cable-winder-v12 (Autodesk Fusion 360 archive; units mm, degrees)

design "Cable Winder"
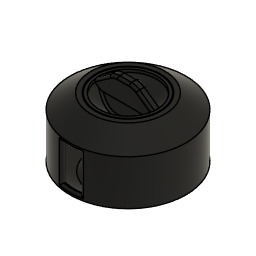
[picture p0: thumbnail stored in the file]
part number: Small Smooth
parameter "radius" = 25
parameter "height" = 32
parameter "gap" = 0.35
sketch "Skizze" plane through (0, 0, 0) normal (0, 1, 0) x axis (1, 0, 0)
  line L1 (25, 0) -> (0, 0)
  line L2 (25, -9.6981) -> (25, 0)
  line L3 (16, -16) -> (25, -9.6981)
  line L4 (14, -16) -> (16, -16)
  line L5 (23, -8.657) -> (23, 0)
  line L6 (14, -14.9589) -> (23, -8.657)
  line L7 (14, -14.9589) -> (14, -16)
  line L8 (12.45, -16) -> (13.65, -16)
  line L9 (13.65, -14.7767) -> (13.65, -16)
  line L10 (15.6652, -13.3656) -> (13.65, -14.7767)
  line L11 (8, -7.9984) -> (15.6652, -13.3656)
  line L12 (8, 0) -> (8, -7.9984)
  line L13 (12.45, -14.7767) -> (12.45, -16)
  line L14 (5.626, -9.9984) -> (12.45, -14.7767)
  line L15 (0, -9.9984) -> (5.626, -9.9984)
  line L16 (12.45, -14.7767) -> (13.65, -14.7767)
  line L17 (0, 0) -> (0, -9.9984)
  line L18 (0, -16) -> (0, -9.9984)
  line L19 (12.45, -16) -> (0, -16)
  line L20 (0, -7.9984) -> (8, -7.9984)
  line L21 (15.3795, -13.1656) -> (15.3795, -13.5656)
  line L22 (0, 0) -> (0, 9.9984)
  line L23 (0, 7.9984) -> (8, 7.9984)
  line L24 (8, 0) -> (8, 7.9984)
  line L25 (8, 7.9984) -> (15.6652, 13.3656)
  line L26 (12.45, 16) -> (13.65, 16)
  line L27 (0, 16) -> (0, 9.9984)
  line L28 (12.45, 16) -> (0, 16)
  line L29 (13.65, 14.7767) -> (13.65, 16)
  line L30 (15.6652, 13.3656) -> (13.65, 14.7767)
  line L31 (14, 14.9589) -> (14, 16)
  line L32 (14, 16) -> (16, 16)
  line L33 (16, 16) -> (25, 9.6981)
  line L34 (14, 14.9589) -> (23, 8.657)
  line L35 (23, 8.657) -> (23, 0)
  line L36 (25, 9.6981) -> (25, 0)
  line L37 (-2, -9.9984) -> (2, -9.9984)
  line L38 (4.4501, -21.6016) -> (12.45, -16)
  line L39 (0, -21.6016) -> (4.4501, -21.6016)
  line L40 (12.45, 14.7767) -> (12.45, 16)
  line L41 (5.626, 9.9984) -> (12.45, 14.7767)
  line L42 (0, 9.9984) -> (5.626, 9.9984)
  line L43 (-4.4501, -21.6016) -> (-12.45, -16)
  line L44 (0, -21.6016) -> (-4.4501, -21.6016)
  line L45 (-5.626, -9.9984) -> (-12.45, -14.7767)
  line L46 (-12.45, -14.7767) -> (-12.45, -16)
  line L47 (0, -9.9984) -> (-5.626, -9.9984)
  line L48 (0, 9.9984) -> (-5.626, 9.9984)
  line L49 (-5.626, 9.9984) -> (-12.45, 14.7767)
  line L50 (-12.45, 14.7767) -> (-12.45, 16)
  line L51 (-12.45, 16) -> (0, 16)
  line L52 (4, -8) -> (-4, -8)
  line L53 (4, 8) -> (4, -8)
  line L54 (-4, 8) -> (4, 8)
  line L55 (-4, -8) -> (-4, 8)
  line L56 (4, 8) -> (-4, -8)
  line L57 (-4, 8) -> (4, -8)
  point P1 (0, 0)
  point P2 (0, 0)
  point P6 (23, 0)
  point P14 (8, 0)
  point P19 (0, 0)
  point P21 (0, -7.9984)
  point P22 (15.3795, -13.5656)
  point P23 (15.3795, -13.1656)
  point P26 (0, 0)
  point P30 (0, 0)
  point P3 (25, 0)
  point P43 (25, 0)
  point P4 (25, -9.6981)
  point P40 (25, 9.6981)
  point P5 (16, -16)
  point P39 (16, 16)
  point P42 (23, 0)
  point P7 (23, -8.657)
  point P41 (23, 8.657)
  point P8 (14, -16)
  point P37 (14, 16)
  point P9 (14, -14.9589)
  point P38 (14, 14.9589)
  point P10 (13.65, -16)
  point P33 (13.65, 16)
  point P11 (13.65, -14.7767)
  point P36 (13.65, 14.7767)
  point P12 (15.6652, -13.3656)
  point P32 (15.6652, 13.3656)
  point P13 (8, -7.9984)
  point P25 (8, 7.9984)
  point P31 (8, 0)
  point P15 (12.45, -16)
  point P34 (12.45, 16)
  point P17 (5.626, -9.9984)
  point P29 (5.626, 9.9984)
  point P18 (0, -9.9984)
  point P24 (0, 9.9984)
  point P28 (0, 0)
  point P20 (0, -16)
  point P35 (0, 16)
  point P27 (0, 7.9984)
  point P46 (0, -16)
  point P49 (12.45, 16)
  point P16 (12.45, -14.7767)
  point P50 (12.45, 14.7767)
  point P51 (5.626, 9.9984)
  point P52 (0, 9.9984)
  point P53 (-12.45, -16)
  point P56 (-12.45, -14.7767)
  point P57 (-5.626, -9.9984)
  point P58 (0, -9.9984)
  point P47 (4.4501, -21.6016)
  point P54 (-4.4501, -21.6016)
  point P48 (0, -21.6016)
  point P55 (0, -21.6016)
  point P64 (-12.45, 16)
  point P63 (0, 16)
  point P62 (-12.45, 16)
  point P61 (-12.45, 14.7767)
  point P59 (-5.626, 9.9984)
  point P60 (0, 9.9984)
  point P69 (0, 0)
  point P70 (19.4395, -13.5917)
  point P67 (4, 8)
  point P68 (-4, 8)
  point P66 (4, -8)
  coincident P1 P2
  horizontal L1
  perpendicular L1 L2
  perpendicular L2 L4
  coincident L1 P6
  perpendicular L1 L5
  parallel L3 L6
  perpendicular L4 L7
  perpendicular L7 L8
  perpendicular L8 L9
  parallel L6 L10
  coincident L1 P14
  perpendicular L1 L12
  perpendicular L8 L13
  parallel L11 L14
  horizontal L16
  collinear L4 L8
  coincident P1 P19
  perpendicular L1 L17
  perpendicular L8 L18
  perpendicular L13 L19
  coincident L17 P21
  perpendicular L17 L20
  coincident L10 P22
  coincident L11 P23
  vertical L21
  symmetric P1 L1 P26
  symmetric P2 L1 P30
  symmetric P3 L1 P43
  symmetric L1 P4 P40
  symmetric L1 P5 P39
  symmetric L1 P6 P42
  symmetric L1 P7 P41
  symmetric L1 P8 P37
  symmetric L1 P9 P38
  symmetric L1 P10 P33
  symmetric L1 P11 P36
  symmetric L1 P12 P32
  symmetric L1 P13 P25
  symmetric L1 P14 P31
  symmetric L1 P15 P34
  symmetric L1 P17 P29
  symmetric L1 P18 P24
  symmetric L1 P19 P28
  symmetric L1 P20 P35
  symmetric L1 P21 P27
  horizontal L37
  coincident P20 P46
  collinear L15 L37
  perpendicular L18 L39
  symmetric L1 P15 P49
  symmetric L1 P16 P50
  symmetric L1 P17 P51
  symmetric L1 P18 P52
  symmetric P15 L18 P53
  symmetric P16 L18 P56
  symmetric P17 L18 P57
  symmetric P18 L18 P58
  symmetric L18 P47 P54
  symmetric L18 P48 P55
  symmetric P34 L27 P64
  symmetric P35 L27 P63
  symmetric L27 P49 P62
  symmetric L27 P50 P61
  symmetric L27 P51 P59
  symmetric L27 P52 P60
  horizontal L52
  perpendicular L52 L53
  parallel L52 L54
  parallel L53 L55
  coincident L56 P69
  coincident L57 P69
  coincident P30 P69
  coincident L3 P70
  dimension "d43" distance P2 P3 = 25 (= "radius")
  dimension "d45" angle L2 L3 = 125
  dimension "d47" distance L3 L6 = 2
  dimension "d48" distance L2 L5 = 2
  dimension "d49" distance P5 L7 = 2
  dimension "d50" distance L7 L9 = 0.35 (= "gap")
  dimension "d51" distance L6 L10 = 0.35 (= "d50")
  dimension "d52" angle L1 L11 = 35
  dimension "d54" distance L11 L14 = 3
  dimension "d55" distance P10 P15 = 1.2
  dimension "d57" distance P5 P18 = 16
  dimension "d58" distance L1 L19 = 16 (= "height / 2")
  dimension "d59" distance L15 L20 = 2
  dimension "d60" distance P22 P23 = 0.4
  dimension "d61" distance L12 L17 = 8
  dimension "d69" angle L19 L38 = 35
  dimension "d70" distance L19 L39 = 5.6016 (= "d71 - 0.4 mm")
  dimension "d71" distance L15 L19 = 6.0016
  dimension "d84" distance P67 P68 = 8
  dimension "d85" distance P66 P67 = 16
revolve "Drehen1" sketch "Skizze" AlongAngle 360
revolve "Drehen1" sketch "Skizze" AlongAngle 360 bodies "Ring"
ground "Fixieren"
joint "Zusammenfügen" alignAngle 0 alignOffsetX 0 alignOffsetY 0 alignOffsetZ 0
chamfer "Fase1" distance 3 Rotate Angle 45
extrude "Extrusion3" cut sketch "Skizze" profile of L27 L28 L40 L41 L42 L48 L49 L50 L51 distance 4
extrude "Extrusion4" add sketch "Skizze" profile of L13 L14 L15 L18 L19 L37 L38 L39 L43 L44 L45 L46 L47 distance 4
chamfer "Fase2" distance 3 Rotate Angle 45
fillet "Abrundung1" radius 1 6
fillet "Abrundung2" radius 4
fillet "Abrundung5" radius 20
extrude "Extrusion5" cut sketch "Skizze" profile of L1 L17 L20 L22 L23 L52 L53 L54 L55 no distance stored
fillet "Abrundung3" radius 1 1 1 1
fillet "Abrundung1" radius 1 1
fillet "Abrundung4" radius 1
fillet "Abrundung2" radius 0.6
coil_primitive "Grundkörper Spirale" Diameter 50 (= "2 * radius") SectionSize 1 TaperAngle 0 Revolutions 0.2
circular_pattern "C-Anordnung" countU 50 (= "2 * radius / 1 mm") TotalAngle 360
mirror "Spiegeln" mirrorStitchTolerance 0.1
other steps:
extrude "Extrusion1" cut sketch "Skizze" profile of L1 L17 L20 L22 L23 L52 L53 L54 L55 no distance stored
create_component "Komponente erstellen1"
create_component "Komponente erstellen2"
joint_origin "Gelenkursprung1"
joint_origin "Gelenkursprung1"
named bodies: "Core", "Ring"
